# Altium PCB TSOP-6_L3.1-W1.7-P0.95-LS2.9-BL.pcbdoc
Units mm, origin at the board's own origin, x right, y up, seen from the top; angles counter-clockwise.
Board outline 15.95 x 16.09 mm, 2 copper layers (Top Layer, Bottom Layer), stack 0 mm thick; 1 components, 0 nets, 6 pads, 0 vias.
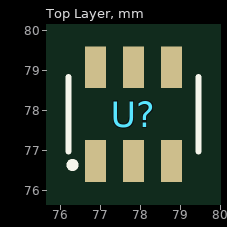
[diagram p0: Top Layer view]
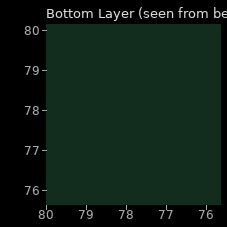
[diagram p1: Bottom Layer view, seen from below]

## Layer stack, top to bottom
Top Layer: signal copper (thickness not stored)
Bottom Layer: signal copper (thickness not stored)

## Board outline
85.802,69.85 69.85,69.85 69.85,85.942 85.802,85.942

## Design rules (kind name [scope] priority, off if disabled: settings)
PasteMaskExpansion "Paste Mask Expansion" [All] p1: expansion=0
SolderMaskExpansion "Solder Mask Expansion" [IsVia] p1: expansion=-25.4 istentingtop=TRUE
SolderMaskExpansion "Solder Mask Expansion" [All] p2: expansion=0.051 istentingtop=FALSE

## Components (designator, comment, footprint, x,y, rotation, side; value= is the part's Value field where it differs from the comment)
U? "" TSOP-6_L3.1-W1.7-P0.95-LS2.9-BL 77.826,77.896 r0 top

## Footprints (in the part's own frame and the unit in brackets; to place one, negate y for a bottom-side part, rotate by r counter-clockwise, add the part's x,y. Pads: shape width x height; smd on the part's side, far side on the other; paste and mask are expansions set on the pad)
TSOP-6_L3.1-W1.7-P0.95-LS2.9-BL [mm]
  rect 0.532x1.046 smd: 1(-0.95,-1.173) 2(0,-1.173) 3(0.95,-1.173) 4(0.95,1.173) 5(0,1.173) 6(-0.95,1.173)
  silkscreen extent -1.63,-1.34 1.63,0.93

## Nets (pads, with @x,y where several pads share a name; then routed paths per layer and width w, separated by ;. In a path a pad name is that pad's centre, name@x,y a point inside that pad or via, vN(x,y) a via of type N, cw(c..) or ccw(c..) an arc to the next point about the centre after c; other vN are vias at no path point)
pads on no net: U?.1 U?.2 U?.3 U?.4 U?.5 U?.6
